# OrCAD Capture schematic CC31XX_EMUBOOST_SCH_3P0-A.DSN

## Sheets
1 3. Rev control
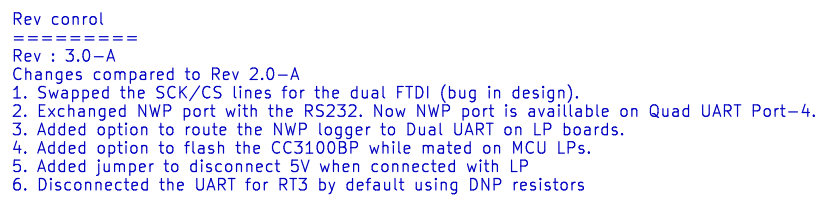
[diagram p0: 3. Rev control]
2 1.QUAD USB: size A2; title: CC31XX FTDI DBG BRD 2.0; rev: B; company: Texas Instruments; note: 66/3 Bagmane Tech Park; note: CV Raman Nagar
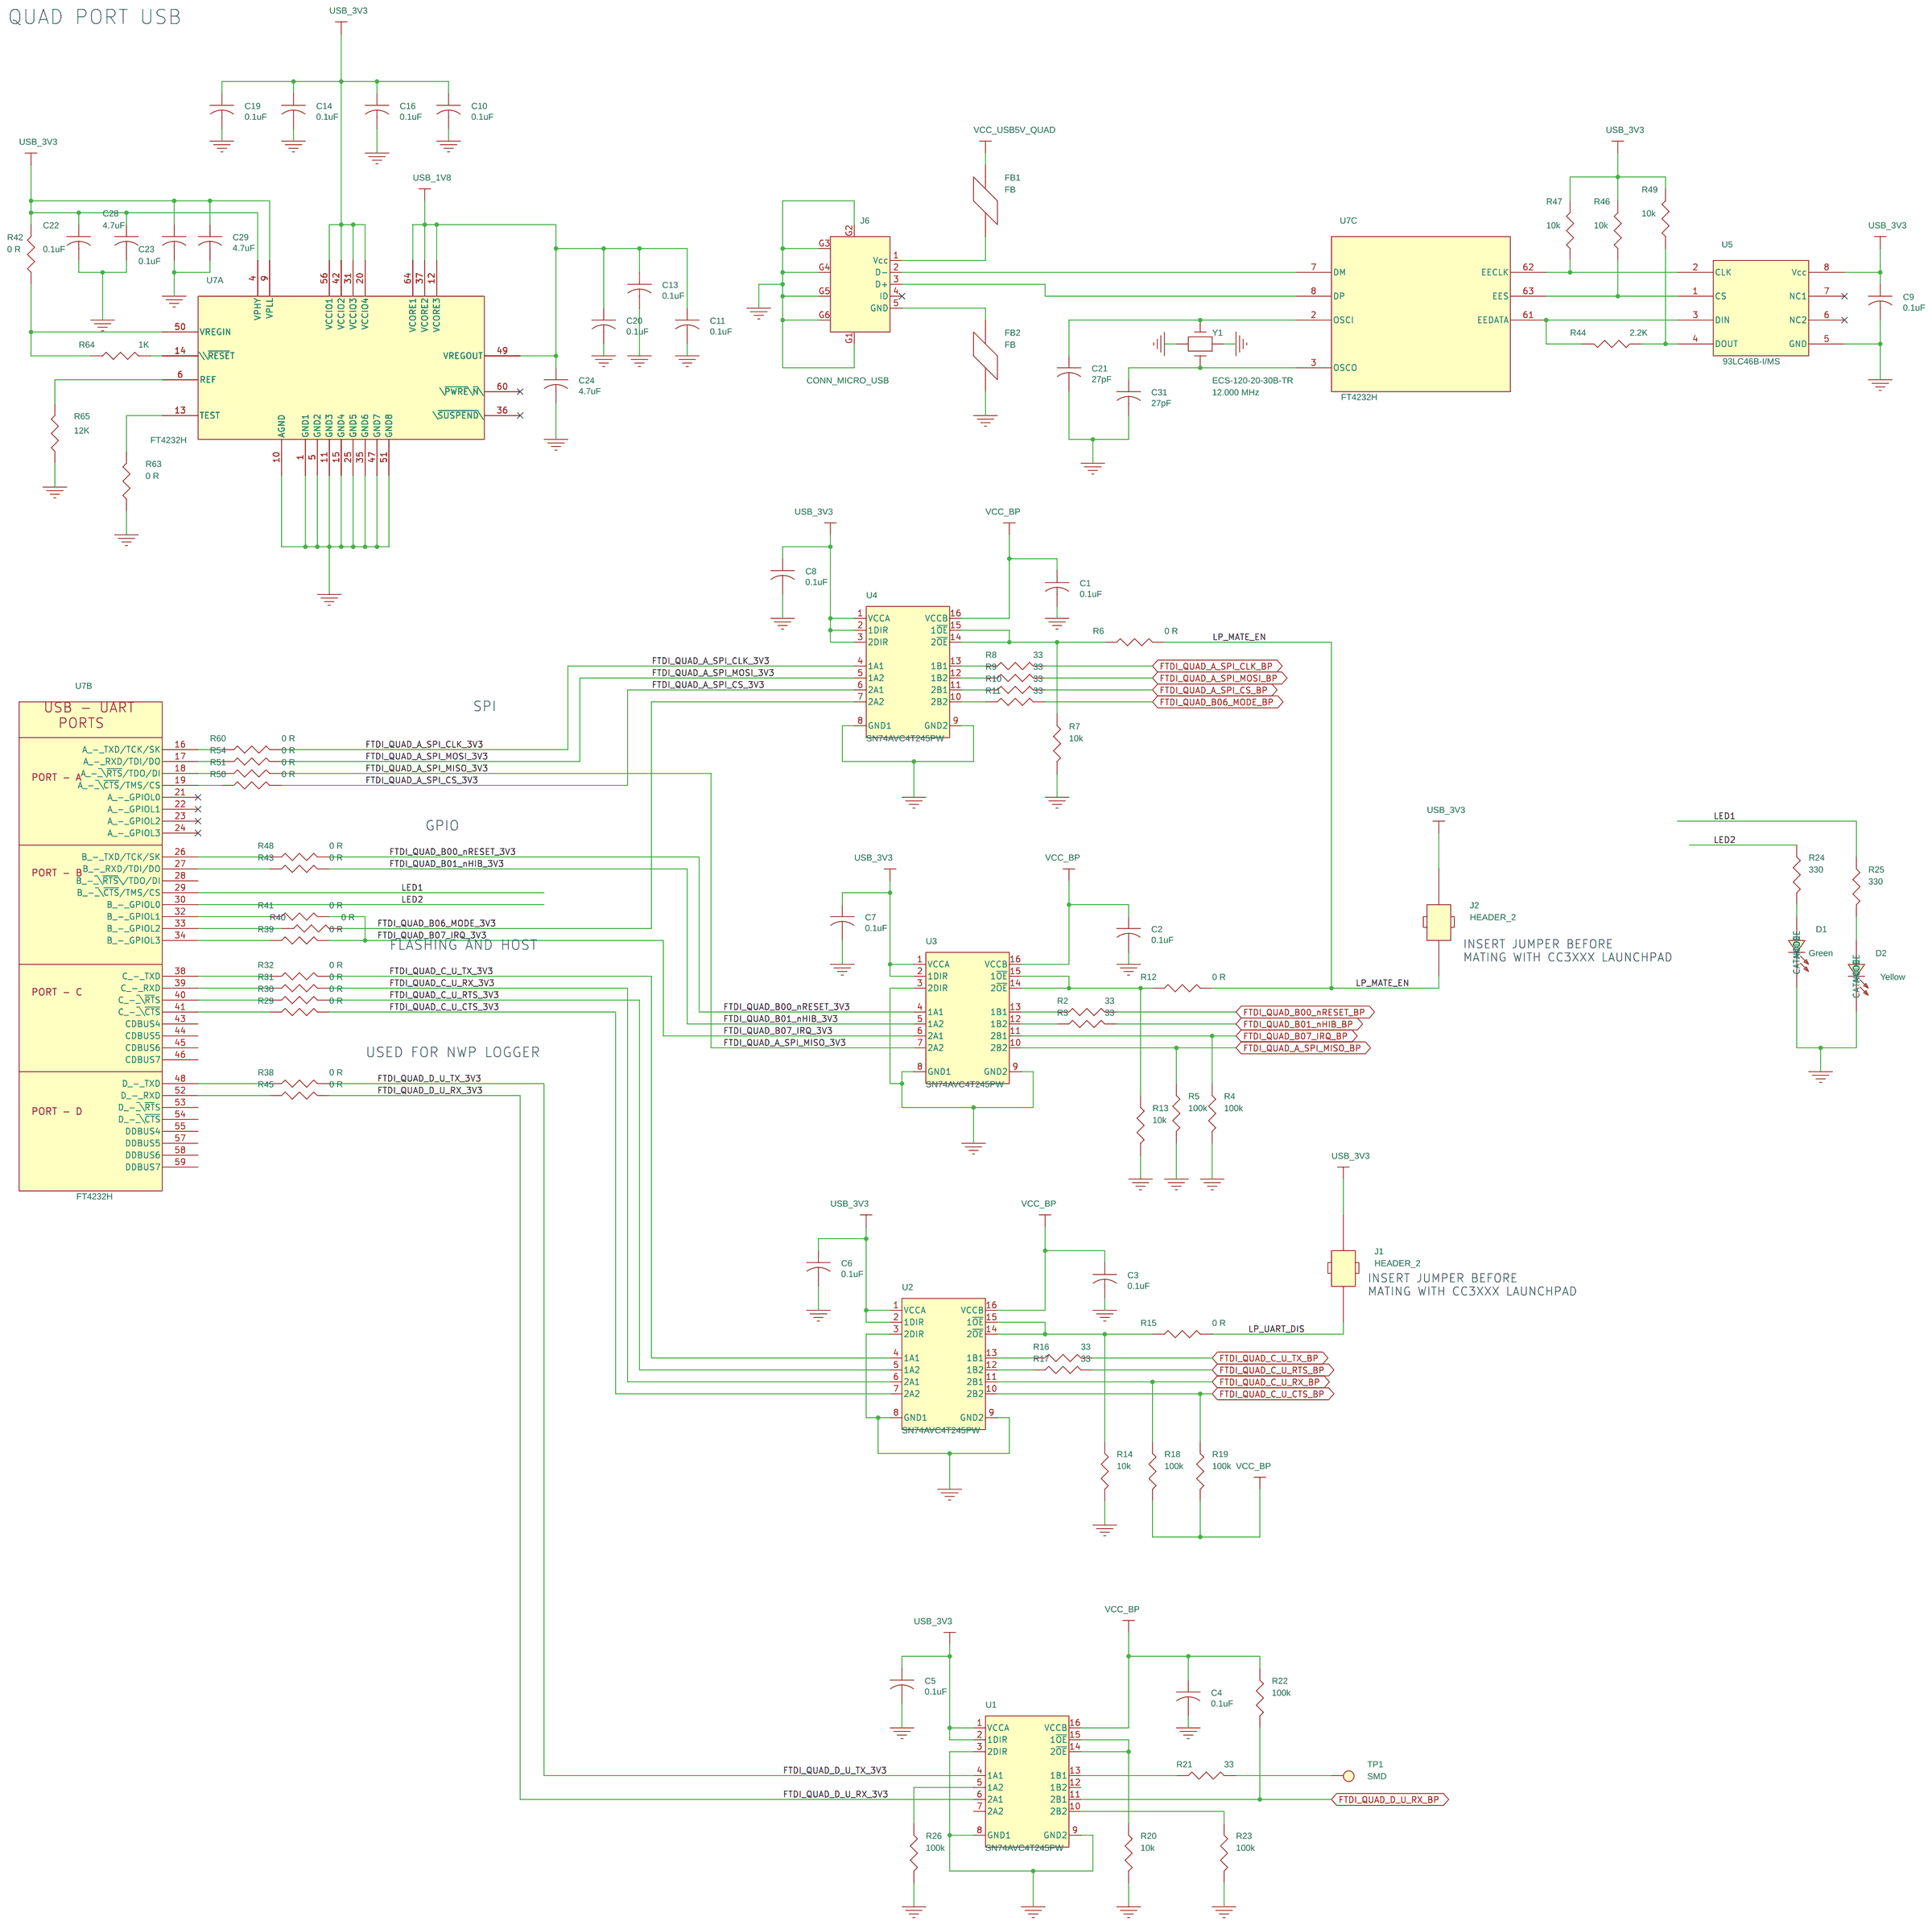
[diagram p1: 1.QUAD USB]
3 2. DUAL USB: size A2; title: CC31XX FTDI DBG BRD 2.0; rev: A; company: Texas Instruments; note: 66/3 Bagmane Tech Park; note: CV Raman Nagar
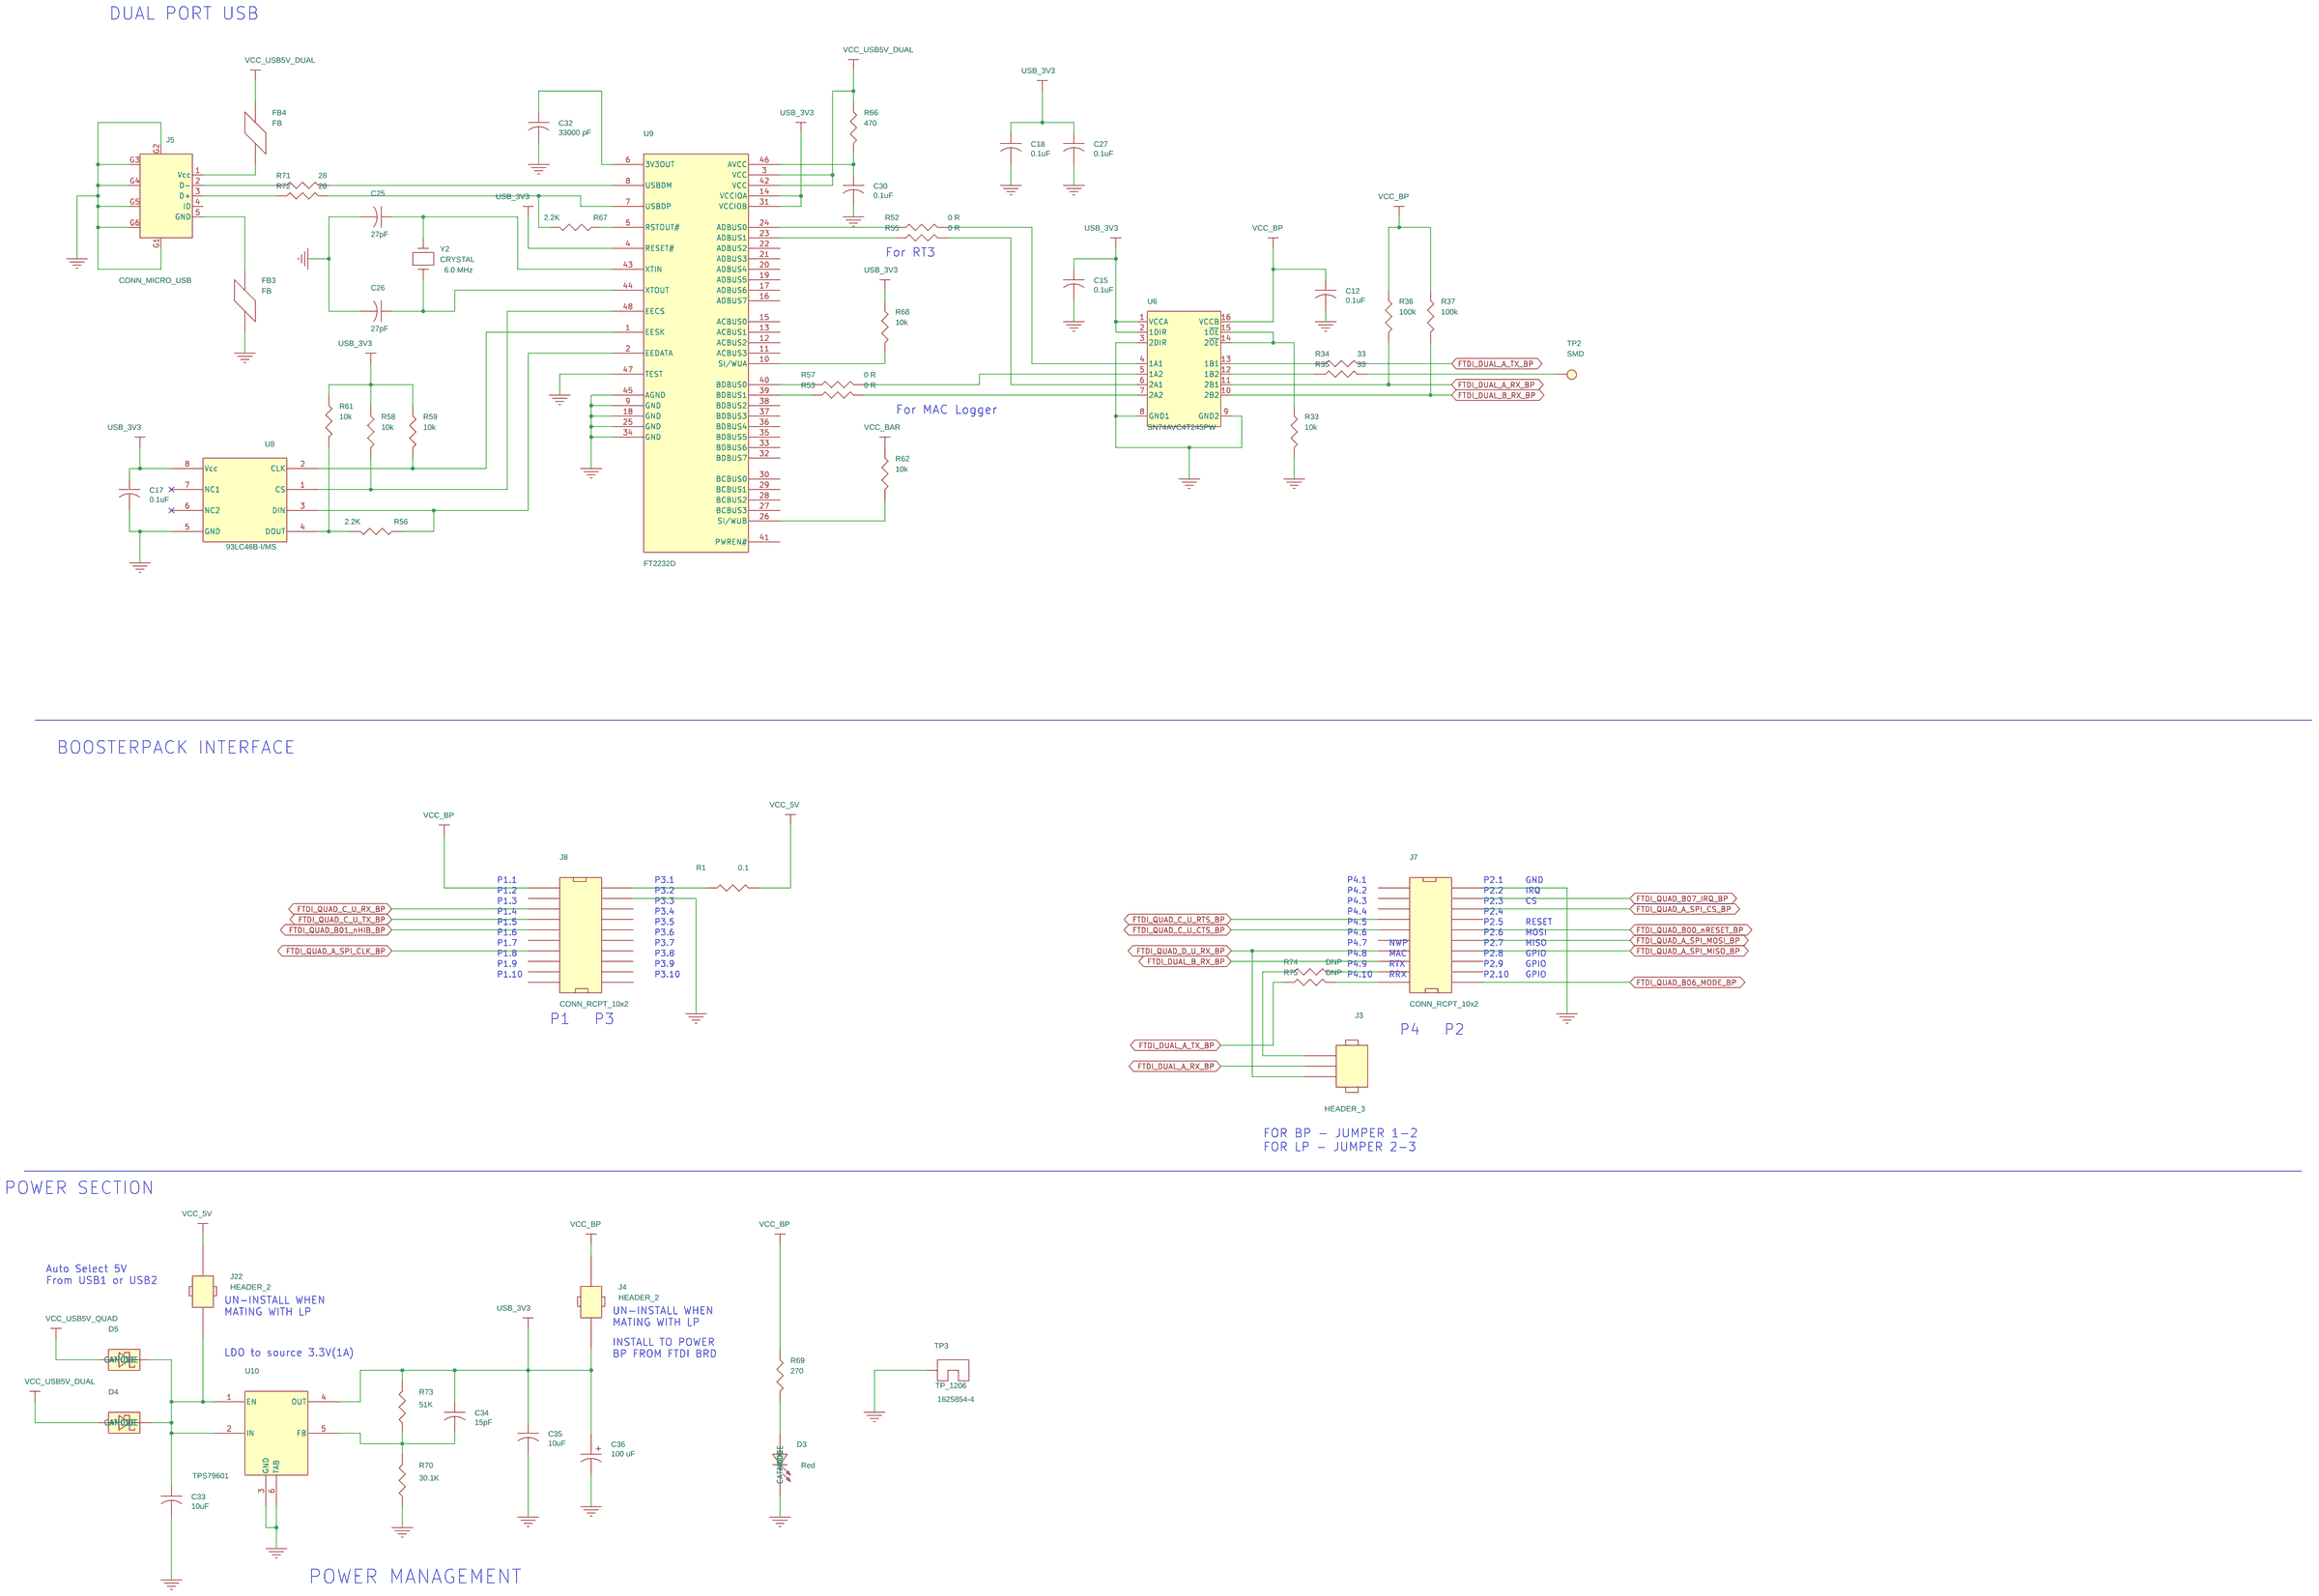
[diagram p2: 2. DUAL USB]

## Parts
sheet 1.QUAD USB
C1  0.1uF  [CC0402]
C2  0.1uF  [CC0402]
C3  0.1uF  [CC0402]
C4  0.1uF  [CC0402]
C5  0.1uF  [CC0402]
C6  0.1uF  [CC0402]
C7  0.1uF  [CC0402]
C8  0.1uF  [CC0402]
C9  0.1uF  [CC0402]
C10  0.1uF  [CC0402]
C11  0.1uF  [CC0402]
C13  0.1uF  [CC0402]
C14  0.1uF  [CC0402]
C16  0.1uF  [CC0402]
C19  0.1uF  [CC0402]
C20  0.1uF  [CC0402]
C21  27pF  [CC0402]
C22  0.1uF  [CC0402]
C23  0.1uF  [CC0402]
C24  4.7uF  [CC0402]
C28  4.7uF  [CC0402]
C29  4.7uF  [CC0402]
C31  27pF  [CC0402]
D1  LED  [LED_0603]
D2  LED  [LED_0603]
FB1  FB  [indc0805]
FB2  FB  [indc0805]
J1  HEADER_2  [HDR_THVT_1x2_100_M]
J2  HEADER_2  [HDR_THVT_1x2_100_M]
J6  CONN_MICRO_USB  [FCI_10118194-0001]
R2  33  [RC0402]
R3  33  [RC0402]
R4  100k  [rc0402]
R5  100k  [rc0402]
R6  0 R  [rc0402]
R7  10k  [rc0402]
R8  33  [RC0402]
R9  33  [RC0402]
R10  33  [RC0402]
R11  33  [RC0402]
R12  0 R  [rc0402]
R13  10k  [rc0402]
R14  10k  [rc0402]
R15  0 R  [rc0402]
R16  33  [RC0402]
R17  33  [RC0402]
R18  100k  [rc0402]
R19  100k  [rc0402]
R20  10k  [rc0402]
R21  33  [RC0402]
R22  100k  [rc0402]
R23  100k  [rc0402]
R24  330  [RC0603]
R25  330  [RC0603]
R26  100k  [rc0402]
R29  0 R  [rc0402]
R30  0 R  [rc0402]
R31  0 R  [rc0402]
R32  0 R  [rc0402]
R38  0 R  [rc0402]
R39  0 R  [rc0402]
R40  0 R  [rc0402]
R41  0 R  [rc0402]
R42  0 R  [rc0402]
R43  0 R  [rc0402]
R44  2.2K  [rc0402]
R45  0 R  [rc0402]
R46  10k  [rc0402]
R47  10k  [rc0402]
R48  0 R  [rc0402]
R49  10k  [rc0402]
R50  0 R  [rc0402]
R51  0 R  [rc0402]
R54  0 R  [rc0402]
R60  0 R  [rc0402]
R63  0 R  [rc0402]
R64  1K  [rc0402]
R65  12K  [rc0402]
TP1  SMD  [TP_SMD_RND_0P5MM]
U1  SN74AVC4T245PW  [TSSOP_16_201x177_26]
U2  SN74AVC4T245PW  [TSSOP_16_201x177_26]
U3  SN74AVC4T245PW  [TSSOP_16_201x177_26]
U4  SN74AVC4T245PW  [TSSOP_16_201x177_26]
U5  93LC46B-I/MS  [TI_MSOP8_0P65_3]
U7  FT4232H  [TI_IC_LQFP64_0P5_10X10]  (sections A,B,C)
Y1  ECS-120-20-30B-TR  [TI_XTAL4_ECS-53B]
sheet 2. DUAL USB
C12  0.1uF  [CC0402]
C15  0.1uF  [CC0402]
C17  0.1uF  [CC0402]
C18  0.1uF  [CC0402]
C25  27pF  [CC0402]
C26  27pF  [CC0402]
C27  0.1uF  [CC0402]
C30  0.1uF  [CC0402]
C32  33000 pF  [cc0402]
C33  10uF  [CC0805]
C34  15pF  [CC0402]
C35  10uF  [CC0805]
C36  100 uF  [TANT_1206]
D3  LED  [LED_0603]
D4  MBR130_SOD-123_2P  [SOD_123FL]
D5  MBR130_SOD-123_2P  [SOD_123FL]
FB3  FB  [indc0805]
FB4  FB  [indc0805]
J3  HEADER_3  [HDR_THVT_1x3_100_M]
J4  HEADER_2  [HDR_THVT_1x2_100_M]
J5  CONN_MICRO_USB  [FCI_10118194-0001]
J7  CONN_RCPT_10x2  [HDR_THVT_2X10_100_F]
J8  CONN_RCPT_10x2  [HDR_THVT_2X10_100_F]
J22  HEADER_2  [HDR_THVT_1x2_100_M]
R1  0.1  [RC0603]
R33  10k  [rc0402]
R34  33  [RC0402]
R35  33  [RC0402]
R36  100k  [rc0402]
R37  100k  [rc0402]
R52  0 R  [rc0402]
R53  0 R  [rc0402]
R55  0 R  [rc0402]
R56  2.2K  [rc0402]
R57  0 R  [rc0402]
R58  10k  [rc0402]
R59  10k  [rc0402]
R61  10k  [rc0402]
R62  10k  [rc0402]
R66  470  [RC0402]
R67  2.2K  [rc0402]
R68  10k  [rc0402]
R69  270  [RC0603]
R70  30.1K  [rc0402]
R71  28  [RC0402]
R72  28  [RC0402]
R73  51K  [rc0402]
R74  DNP  [RC0402]
R75  DNP  [RC0402]
TP2  SMD  [TP_SMD_RND_0P5MM]
TP3  TP_1206  [TP_RCW1206]
U6  SN74AVC4T245PW  [TSSOP_16_201x177_26]
U8  93LC46B-I/MS  [TI_MSOP8_0P65_3]
U9  FT2232D  [QFP_48_284X284_20]
U10  TPS79601  [SOT_223_6_TG]
Y2  CRYSTAL  [xtal_2p_th_1p1mmp]

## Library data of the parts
C1-C8 C12 C15 C17 C18 C27 C30 = C: CAP CER 0.1UF 10V 10% X5R 0402; Distributor_Part_Number: 587-1227-1-ND; Mfr_Name: Taiyo Yuden; Mfr_Part_Number: LMK105BJ104KV-F; TI_Part_No: TI-CAP-LMK105BJ104KV-F; Tolerance: +/-10%; Datasheet: 587-1227-1-ND
C9-C11 C13 C14 C16 C19 C20 C22 C23 = CAP: CAP CER 0.1UF 10V 10% X5R 0402; Distributor_Part_Number: 490-1318-1-ND; Mfr_Name: Murata Electronics North America; Mfr_Part_Number: GRM155R61A104KA01D; Tolerance: ±10%; Voltage_Rating: 10V; Datasheet: http://media.digikey.com/pdf/Data%20Sheets/Murata%20PDFs/GRM%20Series%20Data.pdf
C21 C31 = CAP: CAP CER 27PF 50V 5% NP0 0402; Distributor_Part_Number: 490-5869-1-ND; Mfr_Name: Murata Electronics North America; Mfr_Part_Number: GRM1555C1H270JA01D; Tolerance: ±5%; Voltage_Rating: 50V; Datasheet: http://media.digikey.com/pdf/Data%20Sheets/Murata%20PDFs/GRM%20Series%20Data.pdf
C24 C28 C29 = C: CAP CER 4.7UF 6.3V 20% X5R 0402; Distributor_Part_Number: 1276-1056-2-ND; Mfr_Name: Samsung Electro-Mechanics America, Inc; Mfr_Part_Number: CL05A475MQ5NRNC; TI_Part_No: TI-CAP-CL05A475MQ5NRNC
D1 = LED: LED SMARTLED 560NM PURE GRN 0603; Colour: Green; Distributor_Part_Number: 475-2920-1-ND; Mfr_Name: OSRAM Opto Semiconductors Inc; Mfr_Part_Number: LP L296-J2L2-25-Z; Datasheet: http://catalog.osram-os.com/catalogue/catalogue.do;jsessionid=02CFC813D7820A385840E39BD60DF2B7?act=downloadFile&favOid=020000010003f616000100b6
D2 = LED: LED CHIPLED 587NM YLW 0603 SMD; Colour: Yellow; Distributor_Part_Number: 475-2558-1-ND; Mfr_Name: OSRAM Opto Semiconductors Inc; Mfr_Part_Number: LY Q976-P1S2-36; Datasheet: http://catalog.osram-os.com/jsp/download.jsp?name=LO_LS_LY_Q976.pdf&url=/media/_en/Graphics/00043804_0.pdf
FB1-FB4 = FERRITE_BEAD: FERRITE 1.5A 40 OHM 0805 SMD; Distributor_Part_Number: 240-2389-1-ND; Mfr_Name: Laird-Signal Integrity Products; Mfr_Part_Number: MI0805K400R-10; TI_Part_No: TI-FB-MI0805K400R-10
J1 J2 J4 J22 = HEADER_1X2: CONN HEADR BRKWAY .100 2POS STR; Distributor_Part_Number: 5-146285-2-ND; Mfr_Name: TE Connectivity; Mfr_Part_Number: 5-146285-2; TI_Part_No: TI-CON-5-146285-2; Datasheet: http://www.te.com/commerce/DocumentDelivery/DDEController?Action=srchrtrv&DocNm=146285&DocType=Customer+Drawing&DocLang=English
J5 J6 = CONN_MICRO_USB_5P_6G: CONN USB MICRO B RECPT SMT R/A; Distributor_Part_Number: 609-4618-1-ND; Mfr_Name: FCI; Mfr_Part_Number: 10118194-0001LF; TI_Part_No: TI-CON-10118194-0001LF
R2 R3 R8-R11 R16 R17 R21 R34 R35 = R: RES 33.0 OHM 1/16W 1% 0402 SMD; Distributor_Part_Number: 311-33.0LRCT-ND; Mfr_Name: Yageo; Mfr_Part_Number: RC0402FR-0733RL; Tolerance: ±1%; Datasheet: http://www.yageo.com/documents/recent/PYu-RC0402_51_RoHS_L_6.pdf
R4 R5 R18 R19 R22 R23 R26 R36 R37 = R: RES 100K OHM 1/16W 5% 0402 SMD; Distributor_Part_Number: 311-100KJRCT-ND; Mfr_Name: Yageo; Mfr_Part_Number: RC0402JR-07100KL; Tolerance: 5%
R6 R12 R15 R29-R32 R38-R41 R43 R45 R48 R50-R55 R57 R60 R63 = RESISTOR: RES 0.0 OHM 1/10W JUMP 0402 SMD; Assembly: (NC); Distributor: Digi-Key; Distributor_Name: Digi-Key; Distributor_Part_Number: P0.0JTR-ND; Mfr_Name: Panasonic Electronic Components; Mfr_Part_Number: ERJ-2GE0R00X; TI_Part_No: TI-Panasonic-ERJ-2GE0R00X
R7 R13 R14 R20 R33 R58 R59 R61 R62 R68 = RESISTOR: RES 10K OHM 1/16W 5% 0402 SMD; Distributor_Part_Number: 311-10KJRCT-ND; Mfr_Name: Yageo; Mfr_Part_Number: RC0402JR-0710KL; TI_Part_No: TI-RES-RC0402JR-0710KL; Tolerance: 5%
R24 R25 = RESISTOR: RES 330 OHM 1/10W 5% 0603 SMD; Distributor_Part_Number: P330GCT-ND; Mfr_Name: Panasonic Electronic Components; Mfr_Part_Number: ERJ-3GEYJ331V; Tolerance: ±5%; Datasheet: http://industrial.panasonic.com/www-cgi/jvcr13pz.cgi?E+PZ+3+AOA0001+ERJ3GEYJ331V+7+WW
R42 = RESISTOR: RES 0.0 OHM 1/10W JUMP 0402 SMD; Distributor_Part_Number: P0.0JTR-ND; Mfr_Name: Panasonic Electronic Components; Mfr_Part_Number: ERJ-2GE0R00X; TI_Part_No: TI-Panasonic-ERJ-2GE0R00X
R44 R56 R67 = RESISTOR: RES 2.2K OHM 1/10W 5% 0402 SMD; Distributor_Part_Number: ERJ-2GEJ222X; Mfr_Name: Panasonic; Mfr_Part_Number: ERJ-2GEJ222X; Part Number: ERJ-2GEJ222X; TI_Part_No: TI-RES-ERJ-2GEJ222X
R46 R47 R49 = RESISTOR: RES 10K OHM 1/16W 5% 0402 SMD; Distributor_Part_Number: 311-10KJRCT-ND; Mfr_Name: Yageo; Mfr_Part_Number: RC0402JR-0710KL; Package: EIA-0402; Part Number: RR0510P-103-D; TI_Part_No: TI-RES-RC0402JR-0710KL; Tolerance: 5%
R64 = RESISTOR: RES 1.0K OHM 1/10W 5% 0402 SMD; Distributor_Part_Number: ERJ-2GEJ102X; Mfr_Name: Panasonic - ECG; Mfr_Part_Number: ERJ-2GEJ102X; TI_Part_No: TI-RES-; Tolerance: 5%
R65 = RESISTOR: RES 12.0K OHM 1/16W .5% 0402 SMD; Distributor_Part_Number: RR0510P-123-D; Mfr_Name: Susumu Co; Mfr_Part_Number: RR0510P-123-D; TI_Part_No: TI-RES-; Tolerance: 1%
TP1 TP2 = TP_SMD_RND_0P5MM: TEST PAD SMD CIR 0.5mm; Distributor_Part_Number: TI-TP-SMD-CIR-0P5MM; Mfr_Name: -NA-; Mfr_Part_Number: TI-TP-SMD-CIR-0P5MM; TI_Part_No: TI-TP-SMD-CIR-0P5MM; Datasheet: NA
U1-U4 U6 = SN74AVC4T245PW: Mfr_Name: Texas Instruments
U5 U8 = EEPROM-93C46B_4: IC SRL EE 1K 64X16 2.5V 8MSOP; Distributor_Part_Number: TI-IC-93LC46B-I/MS; Mfr_Name: Microchip; TI_Part_No: TI-IC-93LC46B-I/MS
U7 = FT4232H: IC USB UART/MPSSE QUAD HS 64LQFP; Distributor_Part_Number: TI-IC-FT4232HL; Mfr_Name: FTDI; Mfr_Part_Number: FT4232HL; Part Number: FT4232HL; TI_Part_No: TI-IC-FT4232HL
Y1 = ZTA_0: CRYSTAL 12.000 MHZ 20PF SMD; Distributor_Part_Number: XC1118CT-ND; Frequency: 12.000 MHz; Mfr_Name: ECS; TI_Part_No: TI-XTAL-ECS-120-20-30B-TR
C25 C26 = CAP: CAP CER 27PF 25V 5% NP0 0402; Distributor_Part_Number: 490-6176-1-ND; Mfr_Name: Murata Electronics North America; Mfr_Part_Number: GRM1555C1E270JA01D; Tolerance: ±5%; Voltage_Rating: 25V; Datasheet: http://www.murata.com/products/catalog/pdf/c02e.pdf
C32 = CAP: CAP 33000PF 16V CERAMIC X7R 0402; Distributor_Part_Number: 1276-1555-1-ND; Mfr_Name: Samsung; Mfr_Part_Number: CL05B333KO5NFNC; TI_Part_No: TI-CAP-CL05B333KO5NFNC; Tolerance: 10%; Voltage_Rating: 16 VDC; Datasheet: http://www.samsungsem.com/servlet/FileDownload?type=spec&file=CL05B333KO5NFNC.pdf
C33 C35 = CAP: CAP CER 10UF 10V 10% X5R 0805; Distributor: Digi-Key; Distributor_Name: Digi-Key; Distributor_Part_Number: 490-1709-2-ND; Mfr_Name: Murata; Mfr_Part_Number: GRM21BR61A106KE19L; TI_Part_No: TI-CAP-GRM21BR61A106KE19L; Tolerance: 10%; Voltage_Rating: 10V
C34 = CAP: CAP CER 15PF 50V 5% NP0 0402; Distributor: Digi-Key; Distributor_Name: Digi-Key; Distributor_Part_Number: 490-5888-1-ND; Mfr_Name: Murata Electronics North America; Mfr_Part_Number: GRM1555C1H150JA01D; TI_Part_No: TI-CAP-GRM1555C1H150JA01D; Tolerance: ±5%; Voltage_Rating: 50V; Datasheet: http://media.digikey.com/pdf/Data%20Sheets/Murata%20PDFs/GRM%20Series%20Data.pdf
C36 = CAP_POL: CAP 100UF 6.3V TANTALUM TEL SMD; Distributor_Part_Number: 511-1498-1-ND; Mfr_Name: Rohm; Mfr_Part_Number: TCTAL0J107M8R; TI_Part_No: TI-CAP-TCTAL0J107M8R; Tolerance: 20%; Voltage_Rating: 6.3 VDC; Datasheet: http://rohmfs.rohm.com/en/products/databook/datasheet/passive/tantalum_capacitor/tantalum_chip_capacitor/tct_al.pdf
D3 = LED: LED SMARTLED RED 630NM 0603 SMD; Colour: Red; Distributor_Part_Number: 475-1195-1-ND; Mfr_Name: OSRAM Opto Semiconductors Inc; Mfr_Part_Number: LS L29K-H1J2-1-Z; Datasheet: http://catalog.osram-os.com/catalogue/catalogue.do;jsessionid=E4F0AA773D08BBBBD3EF9B2D573956A2?act=downloadFile&favOid=0200000600039945000100b6
D4 D5 = MBR130_SOD-123_2P: DIODE SCHOTTKY 30V 1A SOD123; Distributor_Part_Number: MBR130T1GOSCT-ND; ICA_MFR_NAME: ON Semiconductor; ICA_PARTNUM: $$33079249566$$MBR130T1G; Mfr_Name: ON Semiconductor; Mfr_Part_Number: MBR130T1G; TI_Part_No: TI-DIODE-MBR130T1G; Datasheet: http://datasheet.octopart.com/MBR130T1G-ON-Semiconductor-datasheet-8332659.pdf
J3 = HEADER_3: CONN HDR BRKWAY .100 3POS VERT; Distributor_Part_Number: A106719-ND; Mfr_Name: TE Connectivity; Mfr_Part_Number: 5-146282-3; TI_Part_No: TI-CON-5-146282-3; Datasheet: http://www.te.com/commerce/DocumentDelivery/DDEController?Action=srchrtrv&DocNm=146282&DocType=Customer+Drawing&DocLang=English
J7 J8 = CONN_RCPT_0: CONN RCPT .100" 20POS DUAL GOLD; Distributor_Part_Number: SAM1196-10-ND; Mfr_Name: Samtec; Mfr_Part_Number: SSQ-110-03-G-D; TI_Part_No: TI-CON-SSQ-110-03-G-D; Datasheet: http://www.samtec.com/documents/webfiles/cpdf/SSQ-1XX-XX-XXX-X-XX-XXX-XX-X-MKT.pdf
R1 = RESISTOR: RES 0.1 OHM 1/10W 5% 0603 SMD; Distributor_Part_Number: P.10AHCT-ND; Mfr_Name: Panasonic Electronic Components; Mfr_Part_Number: ERJ-3RSJR10V; Tolerance: ±5%; Datasheet: http://industrial.panasonic.com/www-cgi/jvcr13pz.cgi?E+PZ+3+AOA0003+ERJ3RSJR10V+7+WW
R66 = RESISTOR: RES 470 OHM 1/16W 1% 0402 SMD; Distributor_Part_Number: 311-470LRCT-ND; Mfr_Name: Yageo; Mfr_Part_Number: RC0402FR-07470RL; Tolerance: ±1%; Datasheet: http://www.yageo.com/documents/recent/PYu-RC0402_51_RoHS_L_6.pdf
R69 = RESISTOR: RES 270 OHM 1/10W 5% 0603 SMD; Distributor_Part_Number: P270GCT-ND; Mfr_Name: Panasonic Electronic Components; Mfr_Part_Number: ERJ-3GEYJ271V; Tolerance: ±5%; Datasheet: http://industrial.panasonic.com/www-cgi/jvcr13pz.cgi?E+PZ+3+AOA0001+ERJ3GEYJ271V+7+WW
R70 = RESISTOR: RES 30.1K OHM 1/16W 1% 0402 SMD; Distributor: Digi-Key; Distributor_Name: Digi-Key; Distributor_Part_Number: 311-30.1KLRCT-ND; Mfr_Name: Yageo; Mfr_Part_Number: RC0402FR-0730K1L; TI_Part_No: TI-RES-RC0402FR-0730K1L; Tolerance: 1%
R71 R72 = RESISTOR: RES 28.0 OHM 1/16W 1% 0402 SMD; Distributor_Part_Number: 311-28.0LRCT-ND; Mfr_Name: Yageo; Mfr_Part_Number: RC0402FR-0728RL; Tolerance: ±1%; Datasheet: http://www.yageo.com/documents/recent/PYu-RC0402_51_RoHS_L_6.pdf
R73 = RESISTOR: RES 51K OHM 1/16W 1% 0402; Distributor: Digi-Key; Distributor_Name: Digi-Key; Distributor_Part_Number: 1276-4178-1-ND; Mfr_Name: Samsung; Mfr_Part_Number: RC1005F513CS; TI_Part_No: TI-RES-RC1005F513CS; Tolerance: 1%
R74 R75 = R: DO NOT MOUNT; Distributor_Part_Number: TI-RES-DNP-0402; Tolerance: NA
TP3 = TP_1206: 1206 PROBE PAD; Distributor: Digi-Key; Distributor_Name: Digi-Key; Distributor_Part_Number: A106146CT-ND; Mfr_Name: TE Connectivity; Mfr_Part_Number: 1625854-4; TI_Part_No: TI-TP-1625854-4
U9 = FT2232_LQFP_48P: IC, USB UART/FIFO, MPSSE, 12/48MHz, 48-PIN, LQFP; Distributor_Part_Number: TI-IC-FT2232D; ICA_MFR_NAME: FUTURE TECHNOLOGY DEVICES INTERNATIONAL LTD; ICA_PARTNUM: $$2285313$$FT2232D; Mfr_Name: FUTURE TECHNOLOGY DEVICES INTERNATIONAL LTD; TI_Part_No: TI-IC-FT2232D; Datasheet: http://www.ftdichip.com/Documents/DataSheets/DS_FT2232D.pdf
U10 = TPS79601_SOT-223_6P: IC,VREG,LDO,1.2V-5.5V,2.7V-5.5V,--,6PIN,SOT-223; Distributor_Part_Number: 296-13761-2-ND; Mfr_Name: TEXAS INSTRUMENTS INC; Mfr_Part_Number: TPS79601DCQR; TI_Part_No: TI_TPS79601DCQR
Y2 = CRYSTAL: CRYSTAL 6MHZ 18PF THRU; Distributor_Part_Number: SER3409-ND; Frequency: 6.0 MHz; Mfr_Name: Epson; Mfr_Part_Number: CA-301 6.0000M-C:PBFREE

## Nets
GND: C1.2 C2.2 C3.2 C4.2 C5.2 C6.2 C7.2 C8.2 C9.2 C10.2 C11.2 C12.2 C13.2 C14.2 C15.2 C16.2 C17.2 C18.2 C19.2 C20.2 C21.2 C22.2 C23.2 C24.2 C25.2 C26.2 C27.2 C28.2 C29.2 C30.2 C31.2 C32.2 C33.2 C35.2 C36.2 D1.2(CATHODE) D2.2(CATHODE) D3.2(CATHODE) FB2.1 FB3.1 J5.G1 J5.G2 J5.G3 J5.G4 J5.G5 J5.G6 J6.G1 J6.G2 J6.G3 J6.G4 J6.G5 J6.G6 J7.2 J8.4 R4.2 R5.2 R7.2 R13.2 R14.2 R20.2 R23.2 R26.2 R33.2 R63.1 R65.1 R70.1 TP3.1 U1.3(2DIR) U1.8(GND1) U1.9(GND2) U2.3(2DIR) U2.8(GND1) U2.9(GND2) U3.3(2DIR) U3.8(GND1) U3.9(GND2) U4.8(GND1) U4.9(GND2) U5.5(GND) U6.3(2DIR) U6.8(GND1) U6.9(GND2) U7.1(GND1) U7.5(GND2) U7.10(AGND) U7.11(GND3) U7.15(GND4) U7.25(GND5) U7.35(GND6) U7.47(GND7) U7.51(GND8) U8.5(GND) U9.9(GND) U9.18(GND) U9.25(GND) U9.34(GND) U9.45(AGND) U9.47(TEST) U10.3(GND) U10.6(TAB) Y1.2 Y1.4
VCC_5V: J22.1 R1.2
VCC_BP: C1.1 C2.1 C3.1 C4.1 C12.1 J4.1 J8.1 R18.2 R19.2 R22.1 R36.1 R37.1 R69.1 U1.16(VCCB) U2.16(VCCB) U3.16(VCCB) U4.16(VCCB) U6.16(VCCB)
VCC_USB5V_DUAL: D4.1(ANODE) FB4.2 R66.1 U9.3(VCC) U9.42(VCC)
VCC_USB5V_QUAD: D5.1(ANODE) FB1.2
FTDI_DUAL_A_RX_BP: J3.2 R36.2 U6.11(2B1)
FTDI_DUAL_A_TX_BP: R34.2 R75.1
FTDI_DUAL_B_RX_BP: J7.15 R37.2 U6.10(2B2)
FTDI_QUAD_A_SPI_CLK_3V3: R60.2 U4.4(1A1)
FTDI_QUAD_A_SPI_CLK_BP: J8.13 R8.2
FTDI_QUAD_A_SPI_CS_3V3: R50.2 U4.6(2A1)
FTDI_QUAD_A_SPI_CS_BP: J7.6 R10.2
FTDI_QUAD_A_SPI_MISO_3V3: R51.2 U3.7(2A2)
FTDI_QUAD_A_SPI_MISO_BP: J7.14 R5.1 U3.10(2B2)
FTDI_QUAD_A_SPI_MOSI_3V3: R54.2 U4.5(1A2)
FTDI_QUAD_A_SPI_MOSI_BP: J7.12 R9.2
FTDI_QUAD_B00_nRESET_3V3: R48.2 U3.4(1A1)
FTDI_QUAD_B00_nRESET_BP: J7.10 R2.2
FTDI_QUAD_B01_nHIB_3V3: R43.2 U3.5(1A2)
FTDI_QUAD_B01_nHIB_BP: J8.9 R3.2
FTDI_QUAD_B06_MODE_3V3: R40.2 U4.7(2A2)
FTDI_QUAD_B06_MODE_BP: J7.20 R11.2
FTDI_QUAD_B07_IRQ_3V3: R39.2 R41.2 U3.6(2A1)
FTDI_QUAD_B07_IRQ_BP: J7.4 R4.1 U3.11(2B1)
FTDI_QUAD_C_U_CTS_3V3: R29.2 U2.7(2A2)
FTDI_QUAD_C_U_CTS_BP: J7.9 R19.1 U2.10(2B2)
FTDI_QUAD_C_U_RTS_3V3: R30.2 U2.5(1A2)
FTDI_QUAD_C_U_RTS_BP: J7.7 R17.2
FTDI_QUAD_C_U_RX_3V3: R31.2 U2.6(2A1)
FTDI_QUAD_C_U_RX_BP: J8.5 R18.1 U2.11(2B1)
FTDI_QUAD_C_U_TX_3V3: R32.2 U2.4(1A1)
FTDI_QUAD_C_U_TX_BP: J8.7 R16.2
FTDI_QUAD_D_U_RX_3V3: R45.2 U1.6(2A1)
FTDI_QUAD_D_U_RX_BP: J3.3 J7.13 R22.2 U1.11(2B1)
FTDI_QUAD_D_U_TX_3V3: R38.2 U1.4(1A1)
LED1: R25.1 U7.29(B_-~{_}\~{CTS}/TMS/CS)
LED2: R24.1 U7.30(B_-_GPIOL0)
LP_MATE_EN: J2.2 R6.2 R12.2
LP_UART_DIS: J1.2 R15.2
USB_1V8: C11.1 C13.1 C20.1 C24.1 U7.12(VCORE3) U7.37(VCORE2) U7.49(VREGOUT) U7.64(VCORE1)
USB_3V3: C5.1 C6.1 C7.1 C8.1 C9.1 C10.1 C14.1 C15.1 C16.1 C17.1 C18.1 C19.1 C22.1 C23.1 C27.1 C28.1 C29.1 C34.1 C35.1 C36.1 J1.1 J2.1 J4.2 R42.2 R46.2 R47.2 R49.2 R58.1 R59.1 R61.1 R62.1 R68.1 R73.2 U1.1(VCCA) U1.2(1DIR) U2.1(VCCA) U2.2(1DIR) U3.1(VCCA) U3.2(1DIR) U4.1(VCCA) U4.2(1DIR) U4.3(2DIR) U5.8(Vcc) U6.1(VCCA) U6.2(1DIR) U7.4(VPHY) U7.9(VPLL) U7.20(VCCIO4) U7.31(VCCIO3) U7.42(VCCIO2) U7.56(VCCIO1) U8.8(Vcc) U9.4(RESET#) U9.14(VCCIOA) U9.31(VCCIOB) U10.4(OUT)
N01286: R44.1 R49.1 U5.4(DOUT)
N01352: R47.1 U5.2(CLK) U7.62(EECLK)
N01364: R65.2 U7.6(REF)
N01384: C21.1 U7.2(OSCI) Y1.3
N01506: R46.1 U5.1(CS) U7.63(EES)
N01570: C31.1 U7.3(OSCO) Y1.1
N01960: R44.2 U5.3(DIN) U7.61(EEDATA)
N02002: R63.2 U7.13(TEST)
N02098: J6.3(D+) U7.8(DP)
N02410: R42.1 R64.1 U7.50(VREGIN)
N02574: R64.2 U7.14(\\~{RESE}T)
N226875: FB1.1 J6.1(Vcc)
N226931: FB2.2 J6.5(GND)
N227919: J6.2(D-) U7.7(DM)
N230114: FB4.1 J5.1(Vcc)
N230138: FB3.2 J5.5(GND)
N230650: R56.1 R61.2 U8.4(DOUT)
N230686: R59.2 U8.2(CLK) U9.1(EESK)
N230722: R58.2 U8.1(CS) U9.48(EECS)
N230850: R56.2 U8.3(DIN) U9.2(EEDATA)
N232459: C26.1 U9.44(XTOUT) Y2.1
N232466: C25.1 U9.43(XTIN) Y2.2
N232899: J5.2(D-) R71.1
N233111: J5.3(D+) R72.1
N233117: R71.2 U9.8(USBDM)
N233261: R67.1 R72.2 U9.7(USBDP)
N233354: C32.1 U9.6(3V3OUT)
N233745: C30.1 R66.2 U9.46(AVCC)
N234481: R67.2 U9.5(RSTOUT#)
N234666: R62.2 U9.26(SI/WUB)
N234693: R68.2 U9.10(SI/WUA)
N238775: R48.1 U7.26(B_-_TXD/TCK/SK)
N238779: R43.1 U7.27(B_-_RXD/TDI/DO)
N238807: R41.1 U7.32(B_-_GPIOL1)
N238860: R32.1 U7.38(C_-_TXD)
N238864: R31.1 U7.39(C_-_RXD)
N238868: R30.1 U7.40(C_-~{_}\~{RT}S)
N238872: R29.1 U7.41(C_-~{_}\~{CTS})
N238924: R38.1 U7.48(D_-_TXD)
N238928: R45.1 U7.52(D_-_RXD)
N239386: R39.1 U7.34(B_-_GPIOL3)
N272217: R53.2 U6.7(2A2)
N292019: R14.1 R15.1 U2.14(2~{OE}) U2.15(1~{OE})
N292933: D1.1(ANODE) R24.2
N292961: D2.1(ANODE) R25.2
N294895: R6.1 R7.1 U4.14(2~{OE}) U4.15(1~{OE})
N295733: R12.1 R13.1 U3.14(2~{OE}) U3.15(1~{OE})
N296706: R20.1 U1.14(2~{OE}) U1.15(1~{OE})
N300466: R50.1 U7.19(A_-~{_}\~{CTS}/TMS/CS)
N300468: R51.1 U7.18(A_-~{_}\~{RTS}/TDO/DI)
N300470: R54.1 U7.17(A_-_RXD/TDI/DO)
N300472: R60.1 U7.16(A_-_TXD/TCK/SK)
N302094: R53.1 U9.39(BDBUS1)
N302821: R23.1 U1.10(2B2)
N310009: R33.1 U6.14(2~{OE}) U6.15(1~{OE})
N310225: R55.2 U6.6(2A1)
N314694: R26.1 U1.5(1A2)
N325704: R40.1 U7.33(B_-_GPIOL2)
N329899: R52.2 U6.4(1A1)
N329904: R57.2 U6.5(1A2)
N334866: R17.1 U2.12(1B2)
N372295: R34.1 U6.13(1B1)
N372693: R52.1 U9.24(ADBUS0)
N372697: R55.1 U9.23(ADBUS1)
N381832: R35.1 U6.12(1B2)
N381852: R57.1 U9.40(BDBUS0)
N393401: R21.1 U1.13(1B1)
N393405: R21.2 TP1.1
N393465: R2.1 U3.13(1B1)
N393469: R3.1 U3.12(1B2)
N393541: R16.1 U2.13(1B1)
N393687: R11.1 U4.10(2B2)
N393689: R10.1 U4.11(2B1)
N393691: R9.1 U4.12(1B2)
N393693: R8.1 U4.13(1B1)
N407737: J8.2 R1.1
N408139: J3.1 R74.1
N408257: C33.1 D4.2(CATHODE) D5.2(CATHODE) J22.2 U10.1(EN) U10.2(IN)
N408297: C34.2 R70.2 R73.1 U10.5(FB)
N408485: D3.1(ANODE) R69.2
N415889: R35.2 TP2.1
N437475: J7.19 R75.2
N437479: J7.17 R74.2

Not connected (* = marked no-connect by the designer): J5 4(ID); J6 4(ID)*; J7 1 3 5 8 11 16 18; J8 3 6 8 10 11 12 14 15 16 17 18 19 20; U1 7(2A2) 12(1B2); U5 6(NC2)* 7(NC1)*; U7 21(A_-_GPIOL0)* 22(A_-_GPIOL1)* 23(A_-_GPIOL2)* 24(A_-_GPIOL3)* 28(B_-~{_}\~{RTS}\/TDO/DI) 36(\~{SUSPEND}\)* 43(CDBUS4) 44(CDBUS5) 45(CDBUS6) 46(CDBUS7) 53(D_-~{_}\~{RT}S) 54(D_-~{_}\~{CTS}) 55(DDBUS4) 57(DDBUS5) 58(DDBUS6) 59(DDBUS7) 60(\~{PWRE}\~{N}\)*; U8 6(NC2)* 7(NC1)*; U9 11(ACBUS3) 12(ACBUS2) 13(ACBUS1) 15(ACBUS0) 16(ADBUS7) 17(ADBUS6) 19(ADBUS5) 20(ADBUS4) 21(ADBUS3) 22(ADBUS2) 27(BCBUS3) 28(BCBUS2) 29(BCBUS1) 30(BCBUS0) 32(BDBUS7) 33(BDBUS6) 35(BDBUS5) 36(BDBUS4) 37(BDBUS3) 38(BDBUS2) 41(PWREN#)

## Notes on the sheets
sheet 1
- Rev conrol
  =========
  Rev : 3.0-A
  Changes compared to Rev 2.0-A
  1. Swapped the SCK/CS lines for the dual FTDI (bug in design).
  2. Exchanged NWP port with the RS232. Now NWP port is availlable on Quad UART Port-4.
  3. Added option to route the NWP logger to Dual UART on LP boards.
  4. Added option to flash the CC3100BP while mated on MCU LPs.
  5. Added jumper to disconnect 5V when connected with LP
  6. Disconnected the UART for RT3 by default using DNP resistors
sheet 2
- QUAD PORT USB
- SPI
- GPIO
- FLASHING AND HOST
- INSERT JUMPER BEFORE
  MATING WITH CC3XXX LAUNCHPAD
- USED FOR NWP LOGGER
- INSERT JUMPER BEFORE
  MATING WITH CC3XXX LAUNCHPAD
sheet 3
- DUAL PORT USB
- For RT3
- For MAC Logger
- BOOSTERPACK INTERFACE
- P1.1
- P3.1
- P4.1
- P2.1
- GND
- P1.2
- P3.2
- P4.2
- P2.2
- IRQ
- P1.3
- P3.3
- P4.3
- P2.3
- CS
- P1.4
- P3.4
- P4.4
- P2.4
- P1.5
- P3.5
- P4.5
- P2.5
- RESET
- P1.6
- P1.7
- P3.6
- P3.7
- P4.6
- P4.7
- NWP
- P2.6
- P2.7
- MISO
- MOSI
- P1.8
- P3.8
- P4.8
- MAC
- P2.8
- GPIO
- P1.9
- P3.9
- P4.9
- RTX
- P2.9
- GPIO
- P1.10
- P3.10
- P4.10
- RRX
- P2.10
- GPIO
- P1   P3
- P4   P2
- FOR BP - JUMPER 1-2
  FOR LP - JUMPER 2-3
- POWER SECTION
- Auto Select 5V
  From USB1 or USB2
- UN-INSTALL WHEN
  MATING WITH LP
- UN-INSTALL WHEN
  MATING WITH LP
- LDO to source 3.3V(1A)
- INSTALL TO POWER
  BP FROM FTDI BRD
- POWER MANAGEMENT
